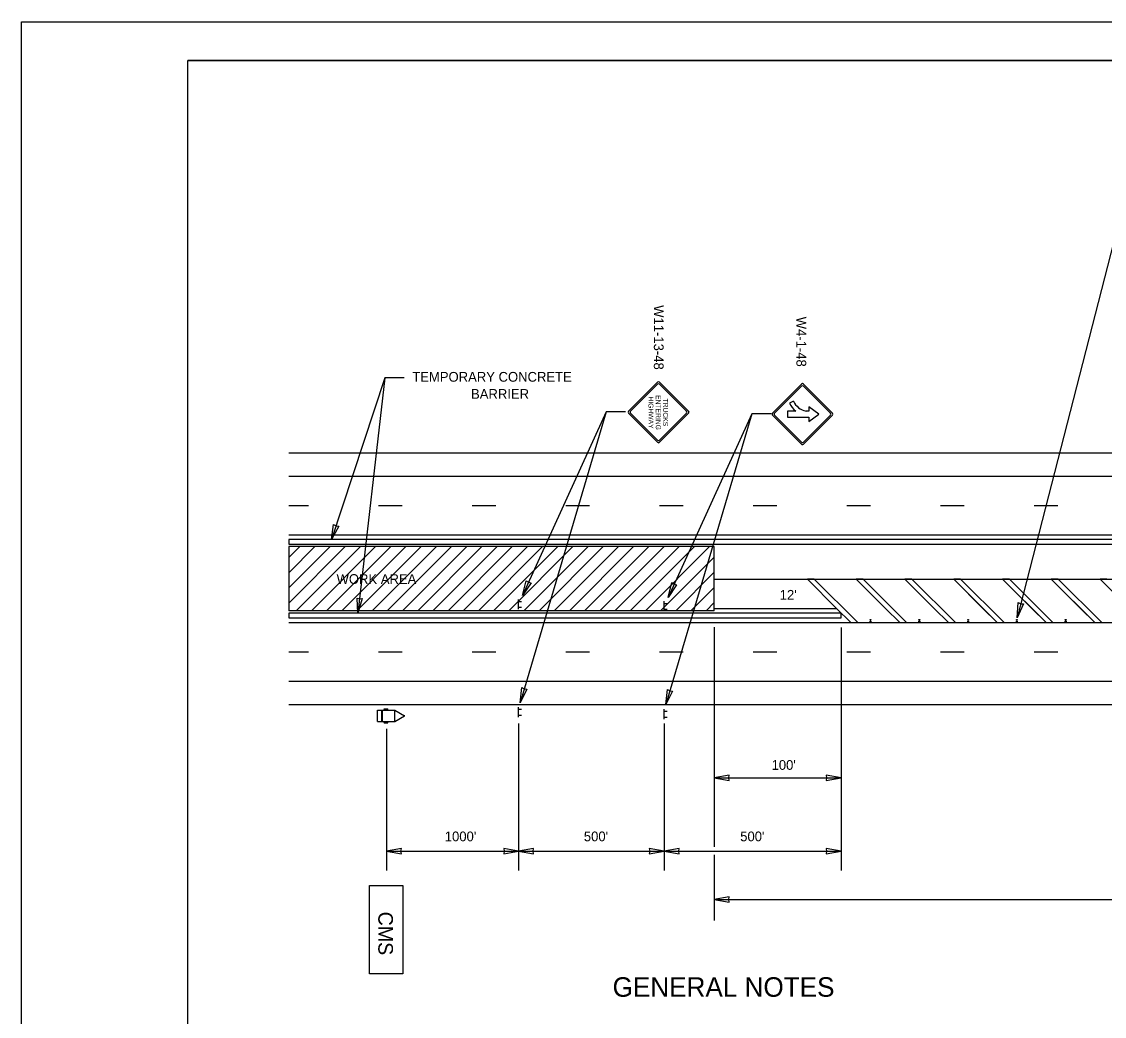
# Model space of a CAD drawing. Extents: x -2433 to -1135, y -5611 to -4633.
# Drawn here: x -2432.9 to -1989.1, y -5040.4 to -4632.8 of the extents above; entities that cross this region are included whole.
import ezdxf

# ---------------------------------------------------------------- set-up
doc = ezdxf.new("R2010")
doc.units = 0
for name, color, linetype in [('Level 4', 7, 'Continuous'), ('Level 42', 7, 'Continuous'), ('Level 45', 7, 'Continuous'), ('Level 46', 7, 'Continuous'), ('Level 47', 7, 'Continuous'), ('Level 48', 7, 'Continuous'), ('Level 49', 7, 'Continuous'), ('Level 5', 7, 'Continuous'), ('Level 50', 7, 'Continuous'), ('TR_WZ_Changeable Message Sign', 7, 'Continuous'), ('TR_WZ_TC_Edge Lines', 7, 'Continuous'), ('TR_WZ_TC_Text and Notes', 7, 'Continuous')]:
    doc.layers.add(name, color=color, linetype=linetype)

msp = doc.modelspace()

# ---------------------------------------------------------------- linework, layer by layer
at = {"layer": 'Level 4'}
for p, q in [((-2184.13, -4792.41), (-2172.26, -4780.54)), ((-2183.29, -4792.41), (-2172.26, -4781.38)), ((-2171.41, -4780.54), (-2159.53, -4792.41)), ((-2171.41, -4781.38), (-2160.38, -4792.41)), ((-2125.17, -4793.17), (-2113.29, -4781.29)), ((-2124.32, -4793.17), (-2113.29, -4782.14)), ((-2112.44, -4781.29), (-2100.56, -4793.17)), ((-2112.44, -4782.14), (-2101.41, -4793.17)), ((-2116.58, -4788.33), (-2118.2, -4789.11)), ((-2184.13, -4793.26), (-2172.26, -4805.14)), ((-2183.29, -4793.26), (-2172.26, -4804.29)), ((-2171.41, -4804.29), (-2160.38, -4793.26)), ((-2171.41, -4805.14), (-2159.53, -4793.26)), ((-2119, -4792.43), (-2119, -4794.83)), ((-2115.53, -4792.43), (-2119, -4792.43)), ((-2110.28, -4792.43), (-2111.4, -4792.43)), ((-2106.14, -4793.63), (-2110.28, -4790.63)), ((-2110.28, -4790.63), (-2110.28, -4792.43)), ((-2125.17, -4794.02), (-2113.29, -4805.9)), ((-2124.32, -4794.02), (-2113.29, -4805.05)), ((-2119, -4794.83), (-2110.28, -4794.83)), ((-2112.44, -4805.05), (-2101.41, -4794.02)), ((-2112.44, -4805.9), (-2100.56, -4794.02)), ((-2110.28, -4796.63), (-2106.14, -4793.63)), ((-2110.28, -4794.83), (-2110.28, -4796.63))]:
    msp.add_line(p, q, dxfattribs=at)
for centre, radius, start, end in [((-2171.83, -4780.96), 0.6, 45.0043, 135), ((-2171.83, -4781.81), 0.6, 45.0021, 135), ((-2112.86, -4781.72), 0.6, 45.0043, 135), ((-2112.86, -4782.56), 0.6, 45.0021, 135), ((-2109.78, -4785.06), 9.34, 205.7188, 232.0643), ((-2109.78, -4785.06), 7.54, 205.7188, 257.6518), ((-2183.71, -4792.84), 0.6, 135, 225), ((-2182.86, -4792.84), 0.6, 135.0015, 225.0016), ((-2160.8, -4792.84), 0.6, 315, 44.9986), ((-2159.95, -4792.84), 0.6, 315, 44.9991), ((-2124.74, -4793.59), 0.6, 135, 225), ((-2123.89, -4793.59), 0.6, 135.0015, 225.0016), ((-2101.83, -4793.59), 0.6, 315, 44.9986), ((-2100.98, -4793.59), 0.6, 315, 44.9991), ((-2171.83, -4803.87), 0.6, 224.9971, 315), ((-2171.83, -4804.72), 0.6, 224.9992, 315), ((-2112.86, -4804.63), 0.6, 224.9971, 315), ((-2112.86, -4805.47), 0.6, 224.9992, 315)]:
    msp.add_arc(centre, radius, start, end, dxfattribs=at)
at = {"layer": 'Level 42'}
for p in [(-1170.57, -4648.81), (-2364.77, -5429.98)]:
    msp.add_line(p, (-2364.77, -4648.78), dxfattribs=at)
msp.add_lwpolyline([(-2364.77, -4648.78), (-1304.73, -4648.78), (-1304.73, -5430.02), (-2364.77, -5430.02)], close=True, dxfattribs=at)
at = {"layer": 'Level 45'}
for p, q in [((-2323.46, -4843.04), (-1810.06, -4843.04)), ((-2085.09, -4878.08), (-2085.09, -4877.76)), ((-2085.09, -4877.76), (-2084.77, -4877.76)), ((-2084.77, -4877.76), (-2084.77, -4878.08)), ((-2065.09, -4878.08), (-2065.09, -4877.76)), ((-2065.09, -4877.76), (-2064.77, -4877.76)), ((-2064.77, -4877.76), (-2064.77, -4878.08)), ((-2045.09, -4878.08), (-2045.09, -4877.76)), ((-2045.09, -4877.76), (-2044.77, -4877.76)), ((-2044.77, -4877.76), (-2044.77, -4878.08)), ((-2025.09, -4878.08), (-2025.09, -4877.76)), ((-2025.09, -4877.76), (-2024.77, -4877.76)), ((-2024.77, -4877.76), (-2024.77, -4878.08)), ((-2005.09, -4878.08), (-2005.09, -4877.76)), ((-2005.09, -4877.76), (-2004.77, -4877.76)), ((-2004.77, -4877.76), (-2004.77, -4878.08)), ((-2323.46, -4879.04), (-1798.16, -4879.04)), ((-2084.77, -4878.08), (-2085.09, -4878.08)), ((-2085.09, -4878.72), (-2085.09, -4878.4)), ((-2085.09, -4878.4), (-2084.77, -4878.4)), ((-2084.77, -4878.72), (-2085.09, -4878.72)), ((-2084.77, -4878.4), (-2084.77, -4878.72)), ((-2064.77, -4878.08), (-2065.09, -4878.08)), ((-2065.09, -4878.72), (-2065.09, -4878.4)), ((-2065.09, -4878.4), (-2064.77, -4878.4)), ((-2064.77, -4878.72), (-2065.09, -4878.72)), ((-2064.77, -4878.4), (-2064.77, -4878.72)), ((-2044.77, -4878.08), (-2045.09, -4878.08)), ((-2045.09, -4878.72), (-2045.09, -4878.4)), ((-2045.09, -4878.4), (-2044.77, -4878.4)), ((-2044.77, -4878.72), (-2045.09, -4878.72)), ((-2044.77, -4878.4), (-2044.77, -4878.72)), ((-2024.77, -4878.08), (-2025.09, -4878.08)), ((-2025.09, -4878.72), (-2025.09, -4878.4)), ((-2025.09, -4878.4), (-2024.77, -4878.4)), ((-2024.77, -4878.72), (-2025.09, -4878.72)), ((-2024.77, -4878.4), (-2024.77, -4878.72)), ((-2004.77, -4878.08), (-2005.09, -4878.08)), ((-2005.09, -4878.72), (-2005.09, -4878.4)), ((-2005.09, -4878.4), (-2004.77, -4878.4)), ((-2004.77, -4878.72), (-2005.09, -4878.72)), ((-2004.77, -4878.4), (-2004.77, -4878.72))]:
    msp.add_line(p, q, dxfattribs=at)
at = {"layer": 'Level 46'}
for p, q in [((-1985.23, -4722.95), (-2024.85, -4877.06)), ((-2284.08, -4778.8), (-2305.94, -4845.04)), ((-2284.08, -4778.8), (-2295.06, -4875.2)), ((-2276.08, -4778.8), (-2284.08, -4778.8)), ((-2193.34, -4792.73), (-2228.6, -4911.84)), ((-2193.34, -4792.73), (-2227.66, -4867.91)), ((-2185.34, -4792.73), (-2193.34, -4792.73)), ((-2133.64, -4793.53), (-2168.89, -4912.64)), ((-2133.64, -4793.53), (-2167.95, -4868.71)), ((-2125.64, -4793.53), (-2133.64, -4793.53)), ((-2323.46, -4809.44), (-1803.64, -4809.44)), ((-2323.46, -4819.04), (-1803.64, -4819.04)), ((-2323.46, -4831.04), (-2315.41, -4831.04)), ((-2286.61, -4831.04), (-2277.01, -4831.04)), ((-2248.21, -4831.04), (-2238.61, -4831.04)), ((-2209.81, -4831.04), (-2200.21, -4831.04)), ((-2171.41, -4831.04), (-2161.81, -4831.04)), ((-2133.01, -4831.04), (-2123.41, -4831.04)), ((-2094.61, -4831.04), (-2085.01, -4831.04)), ((-2056.21, -4831.04), (-2046.61, -4831.04)), ((-2017.81, -4831.04), (-2008.21, -4831.04)), ((-2149.01, -4880.87), (-2149.01, -4970.87)), ((-2097.04, -4881.04), (-2097.04, -4980.64)), ((-2323.46, -4891.04), (-2315.41, -4891.04)), ((-2286.61, -4891.04), (-2277.01, -4891.04)), ((-2248.21, -4891.04), (-2238.61, -4891.04)), ((-2209.81, -4891.04), (-2200.21, -4891.04)), ((-2171.41, -4891.04), (-2161.81, -4891.04)), ((-2133.01, -4891.04), (-2123.41, -4891.04)), ((-2094.61, -4891.04), (-2085.01, -4891.04)), ((-2056.21, -4891.04), (-2046.61, -4891.04)), ((-2017.81, -4891.04), (-2008.21, -4891.04)), ((-2323.46, -4903.04), (-1803.64, -4903.04)), ((-2323.46, -4912.64), (-1803.64, -4912.64)), ((-2229.2, -4920.34), (-2229.2, -4980.64)), ((-2169.49, -4920.34), (-2169.49, -4980.64)), ((-2283.38, -4922.51), (-2283.38, -4980.64)), ((-2149.01, -4942.64), (-2097.04, -4942.64)), ((-2283.38, -4972.64), (-2097.04, -4972.64)), ((-2283.38, -4972.64), (-2110.46, -4972.64)), ((-2149.01, -4974.17), (-2149.01, -5001.03)), ((-2149.01, -4992.52), (-1803.64, -4992.52))]:
    msp.add_line(p, q, dxfattribs=at)
at = {"layer": 'Level 47'}
for p, q in [((-2149.01, -4847.88), (-2323.46, -4847.88)), ((-2323.46, -4847.88), (-2323.46, -4874.2)), ((-2323.46, -4871.06), (-2300.27, -4847.88)), ((-2323.46, -4864.84), (-2306.5, -4847.88)), ((-2323.46, -4858.62), (-2312.72, -4847.88)), ((-2323.46, -4852.4), (-2318.94, -4847.88)), ((-2320.37, -4874.2), (-2294.05, -4847.88)), ((-2314.15, -4874.2), (-2287.83, -4847.88)), ((-2307.93, -4874.2), (-2281.61, -4847.88)), ((-2301.7, -4874.2), (-2275.38, -4847.88)), ((-2295.48, -4874.2), (-2269.16, -4847.88)), ((-2289.26, -4874.2), (-2262.94, -4847.88)), ((-2283.04, -4874.2), (-2256.72, -4847.88)), ((-2276.81, -4874.2), (-2250.49, -4847.88)), ((-2270.59, -4874.2), (-2244.27, -4847.88)), ((-2264.37, -4874.2), (-2238.05, -4847.88)), ((-2258.15, -4874.2), (-2231.83, -4847.88)), ((-2251.92, -4874.2), (-2225.6, -4847.88)), ((-2245.7, -4874.2), (-2219.38, -4847.88)), ((-2239.48, -4874.2), (-2213.16, -4847.88)), ((-2233.26, -4874.2), (-2206.94, -4847.88)), ((-2227.03, -4874.2), (-2200.71, -4847.88)), ((-2220.81, -4874.2), (-2194.49, -4847.88)), ((-2214.59, -4874.2), (-2188.27, -4847.88)), ((-2208.37, -4874.2), (-2182.05, -4847.88)), ((-2202.14, -4874.2), (-2175.82, -4847.88)), ((-2195.92, -4874.2), (-2169.6, -4847.88)), ((-2189.7, -4874.2), (-2163.38, -4847.88)), ((-2183.48, -4874.2), (-2157.16, -4847.88)), ((-2177.25, -4874.2), (-2150.93, -4847.88)), ((-2149.01, -4874.2), (-2149.01, -4847.88)), ((-2171.03, -4874.2), (-2149.01, -4852.18)), ((-2164.81, -4874.2), (-2149.01, -4858.41)), ((-2158.59, -4874.2), (-2149.01, -4864.63)), ((-2152.36, -4874.2), (-2149.01, -4870.85)), ((-2149.01, -4874.2), (-2323.46, -4874.2))]:
    msp.add_line(p, q, dxfattribs=at)
at = {"layer": 'Level 48'}
for p, q in [((-1812.06, -4845.04), (-2323.46, -4845.04)), ((-2323.46, -4845.04), (-2323.46, -4846.96)), ((-2323.46, -4846.96), (-1813.98, -4846.96)), ((-2097.04, -4875.2), (-2323.46, -4875.2)), ((-2323.46, -4875.2), (-2323.46, -4877.12)), ((-2323.46, -4877.12), (-2097.04, -4877.12)), ((-2097.04, -4877.12), (-2097.04, -4875.2))]:
    msp.add_line(p, q, dxfattribs=at)
at = {"layer": 'Level 49'}
for p, q in [((-2305.94, -4845.04), (-2305.04, -4838.87)), ((-2302.98, -4839.55), (-2305.94, -4845.04)), ((-2305.04, -4838.87), (-2304.07, -4839.39)), ((-2304.07, -4839.39), (-2302.98, -4839.55)), ((-2227.66, -4867.91), (-2226.09, -4861.87)), ((-2224.12, -4862.77), (-2227.66, -4867.91)), ((-2226.09, -4861.87), (-2225.19, -4862.5)), ((-2225.19, -4862.5), (-2224.12, -4862.77)), ((-2167.95, -4868.71), (-2166.39, -4862.67)), ((-2164.42, -4863.57), (-2167.95, -4868.71)), ((-2166.39, -4862.67), (-2165.48, -4863.29)), ((-2165.48, -4863.29), (-2164.42, -4863.57)), ((-2295.06, -4875.2), (-2295.44, -4868.97)), ((-2295.44, -4868.97), (-2294.39, -4869.29)), ((-2293.29, -4869.22), (-2295.06, -4875.2)), ((-2294.39, -4869.29), (-2293.29, -4869.22)), ((-2024.85, -4877.06), (-2024.37, -4870.84)), ((-2022.27, -4871.38), (-2024.85, -4877.06)), ((-2024.37, -4870.84), (-2023.37, -4871.29)), ((-2023.37, -4871.29), (-2022.27, -4871.38)), ((-2228.6, -4911.84), (-2227.89, -4905.64)), ((-2225.81, -4906.26), (-2228.6, -4911.84)), ((-2227.89, -4905.64), (-2226.91, -4906.13)), ((-2226.91, -4906.13), (-2225.81, -4906.26)), ((-2168.89, -4912.64), (-2168.19, -4906.44)), ((-2166.11, -4907.06), (-2168.89, -4912.64)), ((-2168.19, -4906.44), (-2167.2, -4906.93)), ((-2167.2, -4906.93), (-2166.11, -4907.06)), ((-2142.87, -4941.56), (-2149.01, -4942.64)), ((-2149.01, -4942.64), (-2142.87, -4943.72)), ((-2143.06, -4942.64), (-2142.87, -4941.56)), ((-2142.87, -4943.72), (-2143.06, -4942.64)), ((-2097.04, -4942.64), (-2103.19, -4941.56)), ((-2103.19, -4941.56), (-2102.99, -4942.64)), ((-2102.99, -4942.64), (-2103.19, -4943.72)), ((-2103.19, -4943.72), (-2097.04, -4942.64)), ((-2277.23, -4971.56), (-2283.38, -4972.64)), ((-2283.38, -4972.64), (-2277.23, -4973.73)), ((-2277.43, -4972.64), (-2277.23, -4971.56)), ((-2277.23, -4973.73), (-2277.43, -4972.64)), ((-2229.2, -4972.64), (-2235.34, -4971.56)), ((-2235.34, -4971.56), (-2235.15, -4972.64)), ((-2235.15, -4972.64), (-2235.34, -4973.73)), ((-2235.34, -4973.73), (-2229.2, -4972.64)), ((-2223.05, -4971.56), (-2229.2, -4972.64)), ((-2229.2, -4972.64), (-2223.05, -4973.73)), ((-2223.25, -4972.64), (-2223.05, -4971.56)), ((-2223.05, -4973.73), (-2223.25, -4972.64)), ((-2169.49, -4972.64), (-2175.64, -4971.56)), ((-2175.64, -4971.56), (-2175.45, -4972.64)), ((-2175.45, -4972.64), (-2175.64, -4973.73)), ((-2175.64, -4973.73), (-2169.49, -4972.64)), ((-2163.34, -4971.56), (-2169.49, -4972.64)), ((-2169.49, -4972.64), (-2163.34, -4973.73)), ((-2163.53, -4972.64), (-2163.34, -4971.56)), ((-2163.34, -4973.73), (-2163.53, -4972.64)), ((-2097.04, -4972.64), (-2103.19, -4971.56)), ((-2103.19, -4971.56), (-2102.99, -4972.64)), ((-2102.99, -4972.64), (-2103.19, -4973.73)), ((-2103.19, -4973.73), (-2097.04, -4972.64)), ((-2142.87, -4991.43), (-2149.01, -4992.52)), ((-2149.01, -4992.52), (-2142.87, -4993.6)), ((-2143.06, -4992.52), (-2142.87, -4991.43)), ((-2142.87, -4993.6), (-2143.06, -4992.52))]:
    msp.add_line(p, q, dxfattribs=at)
at = {"layer": 'Level 5'}
for p, q in [((-2229.2, -4873.58), (-2229.2, -4869.52)), ((-2229.19, -4870.36), (-2228.04, -4870.36)), ((-2229.19, -4872.74), (-2228.04, -4872.74)), ((-2169.49, -4874.38), (-2169.49, -4870.32)), ((-2169.49, -4871.16), (-2168.33, -4871.16)), ((-2169.49, -4873.54), (-2168.33, -4873.54)), ((-2229.2, -4917.76), (-2229.2, -4913.7)), ((-2229.19, -4914.54), (-2228.04, -4914.54)), ((-2229.19, -4916.93), (-2228.04, -4916.93)), ((-2169.49, -4918.56), (-2169.49, -4914.5)), ((-2169.49, -4915.34), (-2168.33, -4915.34)), ((-2169.49, -4917.72), (-2168.33, -4917.72))]:
    msp.add_line(p, q, dxfattribs=at)
at = {"layer": 'Level 50'}
msp.add_lwpolyline([(-2432.94, -4632.82), (-1157.59, -4632.82), (-1157.59, -5447.91), (-2432.94, -5447.91)], close=True, dxfattribs=at)
at = {"layer": 'TR_WZ_Changeable Message Sign'}
for p, q in [((-2287, -4914.96), (-2279.93, -4914.96)), ((-2285.35, -4919.53), (-2285.35, -4914.96)), ((-2284.97, -4919.53), (-2284.97, -4914.96)), ((-2284.33, -4914.82), (-2282.87, -4914.82)), ((-2284.32, -4914.38), (-2282.89, -4914.39)), ((-2279.93, -4919.53), (-2279.93, -4914.96)), ((-2279.93, -4914.96), (-2275.97, -4917.25)), ((-2279.93, -4919.53), (-2275.97, -4917.25)), ((-2287, -4919.53), (-2279.93, -4919.53)), ((-2284.33, -4919.62), (-2282.87, -4919.62)), ((-2284.33, -4920.04), (-2282.87, -4920.04))]:
    msp.add_line(p, q, dxfattribs=at)
msp.add_circle((-2275.94, -4917.25), 0.0403, dxfattribs=at)
for centre, start, end in [((-2284.07, -4914.61), 138.0493, 217.8236), ((-2283.14, -4914.61), 322.1563, 41.9298), ((-2284.07, -4919.83), 142.1099, 218.1063), ((-2283.14, -4919.83), 321.8735, 37.87)]:
    msp.add_arc(centre, 0.337, start, end, dxfattribs=at)
at = {"layer": 'TR_WZ_TC_Edge Lines'}
for p, q in [((-2149.01, -4861.2), (-1808.24, -4861.2)), ((-2108.01, -4861.2), (-2110.84, -4861.2)), ((-2090.17, -4879.04), (-2108.01, -4861.2)), ((-2088.01, -4861.2), (-2090.84, -4861.2)), ((-2070.17, -4879.04), (-2088.01, -4861.2)), ((-2068.01, -4861.2), (-2070.84, -4861.2)), ((-2050.17, -4879.04), (-2068.01, -4861.2)), ((-2033, -4879.04), (-2050.84, -4861.2)), ((-2048.01, -4861.2), (-2050.84, -4861.2)), ((-2030.17, -4879.04), (-2048.01, -4861.2)), ((-2030.17, -4879.04), (-2048.01, -4861.2)), ((-2013, -4879.04), (-2030.84, -4861.2)), ((-2028.01, -4861.2), (-2030.84, -4861.2)), ((-2010.17, -4879.04), (-2028.01, -4861.2)), ((-2010.17, -4879.04), (-2028.01, -4861.2)), ((-2015.37, -4861.2), (-2012.81, -4861.2)), ((-1993, -4879.04), (-2010.84, -4861.2)), ((-2008.01, -4861.2), (-2010.84, -4861.2)), ((-1990.17, -4879.04), (-2008.01, -4861.2)), ((-1990.17, -4879.04), (-2008.01, -4861.2)), ((-1973, -4879.04), (-1990.84, -4861.2)), ((-1988.01, -4861.2), (-1990.84, -4861.2)), ((-2149.01, -4873.2), (-2098.84, -4873.2)), ((-2093, -4879.04), (-2090.17, -4879.04)), ((-2073, -4879.04), (-2070.17, -4879.04)), ((-2053, -4879.04), (-2050.17, -4879.04)), ((-2033, -4879.04), (-2030.17, -4879.04)), ((-2013, -4879.04), (-2010.17, -4879.04)), ((-1993, -4879.04), (-1990.17, -4879.04)), ((-2287, -4919.53), (-2287, -4914.96))]:
    msp.add_line(p, q, dxfattribs=at)
for points in [[(-2110.84, -4861.2), (-2098.84, -4873.2), (-2093, -4879.04)], [(-2090.84, -4861.2), (-2078.84, -4873.2), (-2073, -4879.04)], [(-2070.84, -4861.2), (-2058.84, -4873.2), (-2053, -4879.04)], [(-2050.84, -4861.2), (-2038.84, -4873.2), (-2033, -4879.04)], [(-2030.84, -4861.2), (-2018.84, -4873.2), (-2013, -4879.04)], [(-2010.84, -4861.2), (-1998.84, -4873.2), (-1993, -4879.04)], [(-1990.84, -4861.2), (-1978.84, -4873.2), (-1973, -4879.04)]]:
    msp.add_lwpolyline(points, dxfattribs=at)
msp.add_lwpolyline([(-2276.72, -4986.73), (-2276.72, -5023.01), (-2290.32, -5023.01), (-2290.32, -4986.73)], close=True, dxfattribs=at)

# ---------------------------------------------------------------- texts
at = {"layer": 'Level 42'}
for s, rotation, p in [('W11-13-48', 270, (-2173.77, -4748.98)), ('W4-1-48', 270, (-2115.32, -4753.7)), ('TEMPORARY CONCRETE', 360, (-2272.8, -4780.34)), ('BARRIER', 360, (-2248.71, -4787.34))]:
    msp.add_text(s, height=4, rotation=rotation, dxfattribs=at).set_placement(p)
for s, height, p in [("12'", 4, (-2122.18, -4869.66)), ("1000'", 4, (-2259.48, -4968.63)), ("500'", 4, (-2202.47, -4968.63)), ("500'", 4, (-2138.37, -4968.63)), ('GENERAL NOTES', 8, (-2190.68, -5032.34))]:
    msp.add_text(s, height=height, dxfattribs=at).set_placement(p)
at = {"layer": 'TR_WZ_TC_Edge Lines'}
for s, p in [('WORK AREA', (-2303.84, -4863.19)), ("100'", (-2125.51, -4939.37))]:
    msp.add_text(s, height=4, dxfattribs=at).set_placement(p)
msp.add_text('CMS', height=6, rotation=270, dxfattribs=at).set_placement((-2286.73, -4997.48))
at = {"layer": 'TR_WZ_TC_Text and Notes'}
for s, p in [('HIGHWAY', (-2175.96, -4786.35)), ('ENTERING', (-2172.96, -4785.82)), ('TRUCKS', (-2169.96, -4787.23))]:
    msp.add_text(s, height=2, rotation=270, dxfattribs=at).set_placement(p)

doc.saveas('drawing.dxf')
